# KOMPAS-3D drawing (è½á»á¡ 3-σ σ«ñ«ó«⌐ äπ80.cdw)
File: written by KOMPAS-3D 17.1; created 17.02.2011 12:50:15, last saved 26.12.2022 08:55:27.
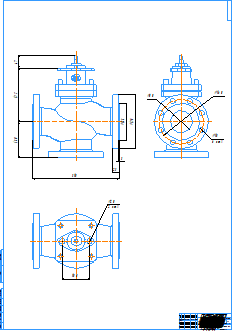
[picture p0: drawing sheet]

Title block, sheet 1: name: Клапан 3-х ходовой Ду80; material: Внимание! Данный продукт является объектом авторского права ООО «Торговый Дом АДЛ». / Запрещается изменение, копирование, распространение / (в том числе путем копирования на другие сайты и ресурсы в Интернете) / или любое иное использование информации и объектов без предварительного / согласия правообладателя (ООО «Торговый Дом АДЛ»).; scale: 1:1; sheets: 1; organisation: ООО "Торговый дом АДЛ"; sheet format: A0; stored path: \\adlc.lan\data\АДЛ_ПКД\3D-модели\ADL production\Клапаны ГРАНРЕГ\Трёхходовой клапан КМ307Ф\KOMPAS 2D\Клапан 3-х ходовой Ду80.cdw

Views: Спереди 1
Dimensions and other numbers on the sheet: 310; 3; 23; 133; 195; 130; 192; 47; 80; 160; 18; 6 отв.; 20; 2 отв.; 100; 1:1; 1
